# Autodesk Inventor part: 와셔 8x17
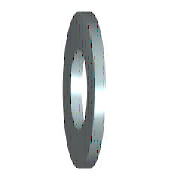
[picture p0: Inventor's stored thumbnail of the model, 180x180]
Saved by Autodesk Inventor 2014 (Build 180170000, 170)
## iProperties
Created: 2012-02
Part Number: 와셔 8x17
Material: 강철, 연강
Description: 평면 와셔
Document SubType Name: Modeling
Standard: KS B 1326
Designer: mduedu
Standards Organization: KS
Language: ko-KR
Size Designation: 8x17
Categories: <MemberInstance><Categories><Category DisplayName="조임쇠" InternalName="e4da775c-781d-43d5-af7c-5136215cf5a6" Mnemonic="FSTN"><Category DisplayName="와셔" InternalN
Density: 1 g/cm^3
Appearance: 파란색 - 벽 페인트 - 광택
IsCustomPart: 1
Author: mduedu
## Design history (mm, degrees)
sketch "스케치"
  geometry: C1 r 8.5 at (0, 0); C2 r 4.5 at (0, 0); 1 further point
  constraints: 2 centre point, 2 coincident
  dimensions: "d0" = 9 diameter of C2 (= SD1); "d1" = 17 diameter of C1 (= SD2)
extrude "본체" new body sketch "스케치" distance "d2" = 1.6 (= SD); taper "d3" = 0 deg
workaxis "Work Axis1"
workplane "Work Plane1"
body "Solid1"
other parameters: "SD1" = 9 [user parameter; used in 1 equation term], "SD2" = 17 [user parameter; used in 1 equation term], "SD" = 1.6 [user parameter; used in 1 equation term], "d4" = 0, "d5" = 0, "d6" = 0, "d7" = 0, "NND" = 8 [user parameter]
